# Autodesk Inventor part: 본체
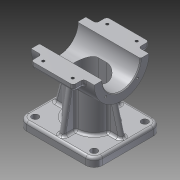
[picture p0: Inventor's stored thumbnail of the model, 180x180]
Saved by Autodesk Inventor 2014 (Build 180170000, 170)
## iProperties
Company: 한국ATC센터
Created: 2014-02
Part Number: 본체
Document SubType Name: Modeling
Designer: KYOUNG IL JANG
Density: 2.71 g/cm^3
Material: 알루미늄-6061
Vendor: CBT Solutions
Mass: 473.206 g
Surface Area: 467.543 cm^2
Volume: 174.615 cm^3
Appearance: 알루미늄 - 평지
Author: KYOUNG IL JANG
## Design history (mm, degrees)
sketch "스케치1"
  geometry: L1 (-45, 40)-(45, 40); L2 (45, 40)-(45, -40); L3 (45, -40)-(-45, -40); L4 (-45, -40)-(-45, 40); 3 further points
  constraints: 8 end point, 2 midpoint, 2 parallel, 1 horizontal, 1 horizontal alignment, 1 perpendicular, 1 vertical alignment
  dimensions: "d0" = 90 distance of L2.end L3.end; "d1" = 80 distance of L1.end L2.end
extrude "돌출1" new body sketch "스케치1" distance "d2" = 10; taper "d3" = 0 deg
sketch "스케치2"
  geometry: L1 (40, 0)-(-40, 0) reference; C1 r 32.5 at (0, 80); 2 further points
  constraints: 1 centre point, 1 midpoint, 1 vertical alignment
  dimensions: "d4" = 65 diameter of C1; "d5" = 80 distance from line of C1.centre L1
extrude "돌출2" join sketch "스케치2" stored distance "d6" = 75; taper "d7" = 0 deg
sketch "스케치3"
  geometry: L1 (-5, -20)-(5, -20); L2 (5, 20)-(-5, 20); A1 r 20 centre (5, 0) between (5, -20) and (5, 20); A2 r 20 centre (-5, 0) between (-5, 20) and (-5, -20); 2 further points
  constraints: 4 end point, 4 point on circle, 4 tangent, 2 centre point, 1 horizontal, 1 horizontal alignment, 1 midpoint, 1 parallel, 1 vertical alignment
  dimensions: "d8" = 20 radius of A2; "d9" = 50 dimension on A1 A2
extrude "돌출3" join sketch "스케치3" stored distance "d10" = 75; taper "d11" = 0 deg
fillet "모깎기1" dims "d12" = 10
sketch "스케치4"
  geometry: L1 (37.5, 47.5)-(-37.5, 47.5) reference; L2 (-40, 10)-(-29.952, 47.5); L3 (-45, 10)-(-35, 10) reference; 1 further point
  constraints: 2 end point, 1 midpoint, 1 point on line
  dimensions: "d105" = 5 distance of L2.start L3.start; "d106" = 75 deg angle of L3 L2
sketch "스케치5"
  geometry: L1 (-35, 10)-(-26.077, 60.603); L2 (-40, 10)-(-30, 10) reference; 2 further points
  constraints: 2 end point, 1 midpoint, 2 other
  dimensions: "d107" = 5 distance of L1.start L2.start; "d108" = 80 deg angle of L2 L1
feature "리브1" dims "d15" = 1, "d16" = 6, "d17" = 0
feature "리브2" dims "d18" = 1, "d19" = 6, "d20" = 0
fillet "모깎기2" dims "d21" = 3
fillet "모깎기3" dims "d22" = 3
fillet "모깎기4" dims "d23" = 3
fillet "모깎기5" dims "d24" = 3
fillet "모깎기6" dims "d25" = 3
fillet "모깎기7" dims "d26" = 3
sketch "스케치6"
  geometry: A1 r 10 centre (35, -30) between (35, -40) and (45, -30) reference; 1 further point
hole "구멍1" sketch "스케치6" at (35, -30) diameter "d28" = 8; stored, may be unused: countersink angle "d32" = 90 deg, drill point angle "d34" = 118 deg; dims "d29" = 6, "d30" = 4, "d31" = 2, "d33" = 8
hole "구멍2" diameter "d37" = 45; stored, may be unused: countersink angle "d41" = 90 deg, drill point angle "d43" = 118 deg; dims "d35" = 10, "d36" = 10, "d38" = 6, "d39" = 4, "d40" = 2, "d42" = 8
sketch "스케치7"
  geometry: C1 r 22.5 at (0, 0) reference; 2 further points
  dimensions: "d44" = 135 deg dimension on C1.centre point (-18.738, 18.738) point (80, 0); "d45" = 26.5 distance of point (-18.738, 18.738) C1.centre
hole "구멍3" sketch "스케치7" at (-18.738, 18.738) diameter "d46" = 2.459; stored, may be unused: countersink angle "d50" = 90 deg, drill point angle "d52" = 118 deg; dims "d47" = 8, "d48" = 4, "d49" = 2, "d51" = 10
node "작업 평면1"
sketch "스케치8"
  geometry: C1 r 10 at (0, 0); 1 further point
  constraints: 1 centre point, 1 coincident
  dimensions: "d57" = 20 diameter of C1
extrude "돌출4" join sketch "스케치8" stored distance "d58" = 75; taper "d59" = 0 deg
hole "구멍4" diameter "d62" = 8.376; stored, may be unused: countersink angle "d66" = 90 deg, drill point angle "d68" = 118 deg; dims "d60" = 10, "d61" = 10, "d63" = 7, "d64" = 4, "d65" = 2, "d67" = 10
chamfer "모따기1" distance "d69" = 1; stored, may be unused: second distance "d70" = 2, angle "d71" = 45 deg
fillet "모깎기9" dims "d72" = 3
sketch "스케치9"
  geometry: L1 (-31.623, 87.5)-(-45, 87.5); L2 (-45, 87.5)-(-45, 72.5); L3 (-45, 72.5)-(-31.623, 72.5); A1 r 32.5 centre (0, 80) between (-31.623, 87.5) and (-31.623, 72.5) reference; 1 further point
  constraints: 6 end point, 2 parallel, 2 point on circle, 1 horizontal, 1 perpendicular
  dimensions: "d73" = 15 distance of L1.end L2.end; "d74" = 45 distance from line of A1.centre L2
extrude "돌출5" join sketch "스케치9" stored distance "d75" = 50; taper "d76" = 0 deg
fillet "모깎기10" dims "d77" = 3
fillet "모깎기11" dims "d78" = 3
sketch "스케치10"
  geometry: L1 (-61.625, 62.366)-(0, 62.366); L2 (0, 62.366)-(0, -62.366); L3 (0, -62.366)-(-61.625, -62.366); L4 (-61.625, -62.366)-(-61.625, 62.366); C1 r 32.5 at (0, 0) reference; 2 further points
  constraints: 8 end point, 2 parallel, 1 coincident, 1 horizontal, 1 midpoint, 1 perpendicular
extrude "돌출6" cut sketch "스케치10" stored distance "d79" = 10; taper "d80" = 0 deg
node "작업 평면2"
sketch "스케치11"
  geometry: L1 (-5, -15)-(5, -15); L2 (5, 15)-(-5, 15); A1 r 15 centre (5, 0) between (5, -15) and (5, 15); A2 r 15 centre (-5, 0) between (-5, 15) and (-5, -15); 9 further points
  constraints: 4 end point, 4 point on circle, 3 tangent, 2 centre point, 1 coincident, 1 horizontal, 1 parallel, 2 other
  dimensions: "d82" = 15 radius of A2; "d109" = 5 dimension on A2; "d110" = 5 dimension on A1
extrude "돌출7" cut sketch "스케치11" stored distance "d83" = 10; taper "d84" = 0 deg
sketch "스케치12"
  geometry: 1 further point
hole "구멍5" sketch "스케치12" at (0, 0) diameter "d85" = 12; stored, may be unused: countersink angle "d89" = 90 deg, drill point angle "d91" = 118 deg; dims "d86" = 6, "d87" = 38, "d88" = 10, "d90" = 8
sketch "스케치13"
  geometry: L1 (-15.5, -12.5)-(-59.5, -12.5) reference; 3 further points
  constraints: 1 horizontal alignment
  dimensions: "d92" = 35 distance of point (-20, -5.5) point (-55, -5.5); "d93" = 17.5 horizontal distance of point (-37.5, 32.5) point (-55, -5.5) (= 0.5 x d92); "d94" = 7 distance from line of L1 point (-55, -5.5)
hole "구멍6" sketch "스케치13" at (-55, -5.5), (-20, -5.5) diameter "d95" = 3.242; stored, may be unused: countersink angle "d99" = 90 deg, drill point angle "d101" = 118 deg; dims "d96" = 6, "d97" = 38, "d98" = 10, "d100" = 8
sketch "스케치14"
  geometry: C1 r 10 at (0, 0); 1 further point
  constraints: 1 centre point, 1 coincident
  dimensions: "d102" = 20 diameter of C1
extrude "돌출8" cut sketch "스케치14" distance "d103" = 5; taper "d104" = 0 deg
fillet "모깎기12" dims "d111" = 3
node "솔리드1"
mirror "대칭1"
mirror "대칭2"
mirror "대칭3"
mirror "대칭4"
pattern_circular "원형 패턴1" dims angle "d54" = 360 deg
mirror "대칭5"
mirror "대칭6"
mirror "대칭7"
other parameters: "d56" = -117
